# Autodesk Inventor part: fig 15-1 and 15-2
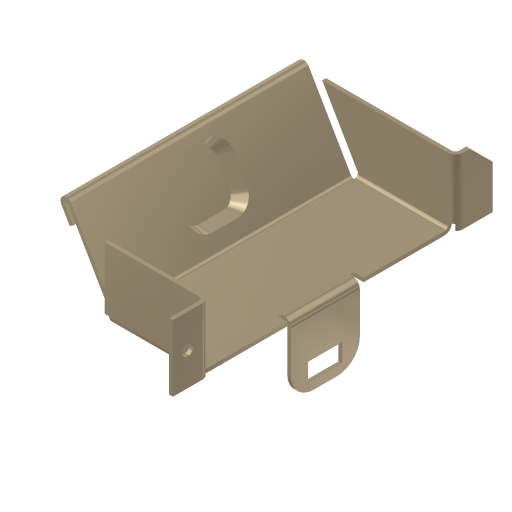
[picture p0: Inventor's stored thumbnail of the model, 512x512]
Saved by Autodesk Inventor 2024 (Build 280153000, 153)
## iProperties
Shininess: 65.0
Angle Display Precision: 2
Document Length Units: 11269
Document Angle Units: 11279
Document Time Units: 11290
Document Mass Units: 11283
Document Length Units Precision: 3
Document Angle Units Precision: 2
Compacted: False
Created: 2002-04
Part Number: fig 15-1 and 15-2
Material: Stainless Steel, 440C
Document SubType Name: Sheet Metal
Density: 1 g/cm^3
Sheet Metal Rule: Default
Appearance: Metal-Titanium (Polished)
Density: 0.0
Volumn: 0.0
Area: 0.0
PropertySet Name: Model Information
Control State: 0
Master: False
Checked Out: False
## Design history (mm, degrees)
node "Face1"
  sketch "Sketch1"
    geometry: L1 (-46.618, 22.343)-(-46.618, -12.657); L2 (-46.618, -12.657)-(53.382, -12.657); L3 (53.382, -12.657)-(53.382, 22.343); L4 (53.382, 22.343)-(35.882, 22.343); L5 (35.882, 22.343)-(35.882, 12.343); L6 (35.882, 12.343)-(-29.118, 12.343); L7 (-29.118, 12.343)-(-29.118, 22.343); L8 (-29.118, 22.343)-(-46.618, 22.343)
    constraints: 16 end point, 6 parallel, 2 equal length, 1 perpendicular, 1 vertical
    dimensions: "d0" = 100 distance of L1.end L2.end; "d1" = 35 distance of L1.start L1.end; "d2" = 65 distance of L5.end L6.end; "d3" = 10 distance of L6.end L7.end
feature "Fold1" dims "d5" = 1 (= BendRadius), "d6" = 90 deg, "d7" = 1 (= BendRadius), "d52" = 1 (= BendReliefWidth), "d53" = 0.5 (= BendReliefDepth), "d54" = 2 (= MinimumRemnant), "d75" = 1 (= Thickness), "SeamGap" = 0.01
feature "Fold2" dims "d8" = 1 (= BendRadius), "d9" = 90 deg, "d10" = 1 (= BendRadius), "d55" = 1 (= BendReliefWidth), "d56" = 0.5 (= BendReliefDepth), "d57" = 2 (= MinimumRemnant), "d75" = 1 (= Thickness), "SeamGap" = 0.01
node "Flange1"
feature "Corner1" dims "d15" = 1 (= Thickness), "d16" = 0, "d73" = 4 (= CornerReliefSize), "d75" = 1 (= Thickness), "TransitionRadius" = 1 (= BendRadius)
feature "Fold3" dims "d17" = 1 (= BendRadius), "d18" = 90 deg, "d19" = 1 (= BendRadius), "d61" = 1 (= BendReliefWidth), "d62" = 0.5 (= BendReliefDepth), "d63" = 2 (= MinimumRemnant), "d75" = 1 (= Thickness), "SeamGap" = 0.01
feature "Fold4" dims "d20" = 1 (= BendRadius), "d21" = 90 deg, "d22" = 1 (= BendRadius), "d64" = 1 (= BendReliefWidth), "d65" = 0.5 (= BendReliefDepth), "d66" = 2 (= MinimumRemnant), "d75" = 1 (= Thickness), "SeamGap" = 0.01
sketch "Sketch6"
  geometry: 1 further point
feature "iFeature4:1" sketch "Sketch6"
feature "Hem2" dims "d32" = 1 (= BendRadius), "d33" = 6 (= 6 x Thickness), "d34" = 1 (= Thickness), "d35" = 0.5 (= 0.5 x d34), "d67" = 1 (= BendReliefWidth), "d68" = 0.5 (= BendReliefDepth), "d69" = 2 (= MinimumRemnant), "d75" = 1 (= Thickness), "SeamGap" = 0.01, "MinimumRemnant" = 2 (= 2 x Thickness), "BendReliefWidth" = 1 (= Thickness)
node "Face2"
  sketch "Sketch9"
    geometry: L1 (0, 0)-(62.738, 0) reference; L2 (40.511, 0)-(22.35, 0); L3 (22.35, 0)-(22.35, 18.987); L4 (22.35, 18.987)-(40.511, 18.987); L5 (40.511, 18.987)-(40.511, 0)
    constraints: 8 end point, 2 parallel, 1 horizontal, 1 perpendicular, 1 point on line
sketch "Sketch10"
  geometry: L1 (13.661, -2.202)-(4.661, -2.202); L2 (4.661, -2.202)-(4.661, -7.127); L3 (4.661, -7.127)-(13.661, -7.127); L4 (13.661, -7.127)-(13.661, -2.202); L5 (18.161, -16.987)-(18.161, 0) reference
  constraints: 8 end point, 2 parallel, 1 horizontal, 1 perpendicular
  dimensions: "d50" = 4.5 distance between parallel lines of L5 L4; "d51" = 9 distance of L1.start L1.end
cut "Cut1" sketch "Sketch10" dims "d38" = 1 (= Thickness), "d39" = 0
sketch "Sketch11"
  geometry: 1 further point
hole "Hole1" sketch "Sketch11" at (3.935, 8.75) diameter "d40" = 3; stored, may be unused: countersink angle "d44" = 82 deg, drill point angle "d46" = 118 deg; dims "d41" = 6, "d42" = 4, "d43" = 2, "d45" = 8
feature "Corner Chamfer1" dims "d47" = 6, "d48" = 6, angle "d74" = 45 deg
feature "Corner Round1" dims "d49" = 6
body "Solid1"
sketch "Sketch2"
  geometry: L1 (100, 0)-(0, 0) reference; L2 (17.5, 35)-(17.5, 25) reference; L3 (17.5, 25)-(17.5, 0); L4 (82.5, 25)-(82.5, 0)
  constraints: 4 end point, 2 point on line, 1 collinear, 1 perpendicular
face "Plate1" dims "d75" = 1 (= Thickness)
sketch "Sketch3"
  geometry: L1 (-62.738, 0)-(-62.738, 25); L2 (-62.738, 25)-(0, 25); 1 other entity
  constraints: 4 end point, 4 other
face "Plate2" dims "d12" = 25, "d13" = 120 deg, "d14" = 1 (= BendRadius), "d75" = 1 (= Thickness), "MinimumRemnant" = 2 (= 2 x Thickness), "BendReliefWidth" = 1 (= Thickness)
bend "Bend1" dims "d11" = 1 (= BendRadius), "d12" = 25, "d13" = 120 deg, "d14" = 1 (= BendRadius), "d58" = 1 (= BendReliefWidth), "d59" = 0.5 (= BendReliefDepth), "d60" = 2 (= MinimumRemnant), "d75" = 1 (= Thickness), "SeamGap" = 0.01, "MinimumRemnant" = 2 (= 2 x Thickness), "BendReliefWidth" = 1 (= Thickness)
sketch "Sketch4"
  geometry: L1 (0, 0)-(0, 35) reference; L2 (15.869, 25)-(15.869, 26) reference; L3 (17.5, 26)-(0, 26)
  constraints: 2 end point, 1 perpendicular, 1 point on line
sketch "Sketch5"
  geometry: L1 (-17.5, -34.296)-(-17.5, 9) reference; L2 (0, 0)-(-17.5, 0)
  constraints: 2 end point, 1 perpendicular, 1 point on line
sketch "Sketch8"
  geometry: L1 (0.866, 0.5)-(0, 0); L2 (-0.866, -0.5)-(1.384, -4.397); L3 (1.384, -4.397)-(0.518, -4.897); L4 (0.518, -4.897)-(-1.732, -1); A1 r 0.5 centre (-0.433, -0.25) between (0, 0) and (-0.866, -0.5); A2 r 1.5 centre (-0.433, -0.25) between (0.866, 0.5) and (-1.732, -1)
  constraints: 8 end point, 4 point on circle
face "Plate3" dims "d36" = 1 (= BendRadius), "d75" = 1 (= Thickness), "MinimumRemnant" = 2 (= 2 x Thickness), "BendReliefWidth" = 1 (= Thickness)
bend "Bend2" dims "d36" = 1 (= BendRadius), "d37" = 1 (= BendRadius), "d70" = 1 (= BendReliefWidth), "d71" = 0.5 (= BendReliefDepth), "d72" = 2 (= MinimumRemnant), "d75" = 1 (= Thickness), "SeamGap" = 0.01, "MinimumRemnant" = 2 (= 2 x Thickness), "BendReliefWidth" = 1 (= Thickness)
other parameters: "Thickness" = 1, "BendRadius" = 1 (= Thickness), "BendReliefDepth" = 0.5 (= 0.5 x Thickness), "CornerReliefSize" = 4 (= 4 x Thickness), "d4" = 1 (= BendRadius), "d27" = 0, "JacobiRadiusSize" = 1 (= Thickness), "GapSize" = 1 (= Thickness)
